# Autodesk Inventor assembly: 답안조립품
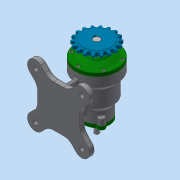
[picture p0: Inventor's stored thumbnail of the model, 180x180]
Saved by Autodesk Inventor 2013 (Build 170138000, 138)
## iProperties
Created: 2017-03
Part Number: 답안조립품
Document SubType Name: Assembly
Designer: dgall
Author: dgall
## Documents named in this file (14)
- C:\Users\dgall\Desktop\470307V1009\답안조립품.iam
- C:\Users\dgall\Desktop\470307V1009\본체.ipt
- C:\Users\dgall\Desktop\470307V1009\뒤커버.ipt
- C:\Users\dgall\Desktop\470307V1009\베어링-6200.ipt
- C:\Users\dgall\Desktop\470307V1009\베어링-6203.ipt
- C:\Users\dgall\Desktop\470307V1009\스프로킷.ipt
- C:\Users\dgall\Desktop\470307V1009\앞커버.ipt
- C:\Users\dgall\Desktop\470307V1009\오일 실 10 20 7.ipt
- C:\Users\dgall\Desktop\470307V1009\오일 실 17 30 8.ipt
- C:\Users\dgall\Desktop\470307V1009\축.ipt
- C:\Users\dgall\Desktop\470307V1009\키5x5.ipt
- C:\Users\dgall\Desktop\470307V1009\볼트 M5 x 10.ipt
- 볼트 M5 x 10.ipt
- C:\Users\dgall\Desktop\470307V1009\볼트 M4 x 12.ipt
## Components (9 placed, 1 different names)
1. ISO 4762 M4 x 12:1
2. ISO 4762 M4 x 12:2
3. ISO 4762 M4 x 12:3
4. ISO 4762 M4 x 12:4
5. ISO 4762 M4 x 12:5
6. ISO 4762 M4 x 12:6
7. ISO 4762 M4 x 12:7
8. ISO 4762 M4 x 12:8
9. ISO 4762 M4 x 12:9
